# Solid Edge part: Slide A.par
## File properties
Author: davee
Template: Normal.par
Last saved by: davee
Revision: 2
Application: Solid Edge
Accuracy: 0.990
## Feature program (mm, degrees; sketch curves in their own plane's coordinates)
body "unnamed Body 1"
sketch for "unnamed Cutout 1" plane through (42.5, 0, 0) normal (0, 0, 1) x-axis (1, 0, 0)
  line (38.4225, -8.5675) -> (-42.5, -8.5675)
  line (38.4225, -71.4325) -> (38.4225, -8.5675)
  line (-42.5, -71.4325) -> (38.4225, -71.4325)
extrude "unnamed Cutout 1" cut to key point along -normal
sketch for "unnamed Cutout 2" #1 plane through (42.5, 0, 0) normal (0, 0, 1) x-axis (1, 0, 0)
  circle centre (20.12, -25.86) radius 2.6929
sketch for "unnamed Cutout 2" #2 plane through (42.5, 0, 0) normal (0, 0, 1) x-axis (1, 0, 0)
  arc centre (20.0176, -33.9386) radius 3.2974 from (16.7201, -33.9386) to (20.0176, -30.6411) cw
  line (20.0176, -30.6411) -> (20.2224, -30.6411)
  arc centre (20.2224, -33.9386) radius 3.2974 from (20.2224, -30.6411) to (23.5199, -33.9386) cw
  line (23.5199, -33.9386) -> (23.5199, -46.0614)
  arc centre (20.2224, -46.0614) radius 3.2974 from (23.5199, -46.0614) to (20.2224, -49.3589) cw
  line (20.2224, -49.3589) -> (20.0176, -49.3589)
  arc centre (20.0176, -46.0614) radius 3.2974 from (20.0176, -49.3589) to (16.7201, -46.0614) cw
  line (16.7201, -46.0614) -> (16.7201, -33.9386)
sketch for "unnamed Cutout 2" #3 plane through (42.5, 0, 0) normal (0, 0, 1) x-axis (1, 0, 0)
  circle centre (20.12, -54.14) radius 2.6929
extrude "unnamed Cutout 2" cut to key point along -normal
sketch for "unnamed Cutout 3" plane through (28.2602, -40, -11.1675) normal (0, 0, 1) x-axis (1, 0, 0)
  line (-30.5996, -17.2339) -> (29.2788, -17.2339)
  line (29.2788, -17.2339) -> (29.2788, 16.4162)
  line (29.2788, 16.4162) -> (-30.5996, 16.4162)
  line (-30.5996, 16.4162) -> (-30.5996, -17.2339)
extrude "unnamed Cutout 3" cut finite 15 along -normal
sketch for "ExtrudedCutout_8" plane through (0, 52.095, -35) normal (-1, 0, 0) x-axis (0, -1, 0)
  line (75.935, 23.8325) -> (108.255, 23.8325)
extrude "ExtrudedCutout_8" cut finite 171.45 along -normal
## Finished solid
Body 1: solid body, 135 faces, 331 edges, 196 vertices.
  Faces by surface: cylinder 62, plane 50, spline 11, sphere 6, torus 6
  Edges by curve: line 200, circle 71, ellipse 45, intersection 10, curve on surface 3, spline 2
Bounding box of the edges (mm; curved faces can reach further): 108.658 x 250.000 x 70.002, from (0, -125, -70.0017) to (108.6581, 125, 0).
Cylindrical faces by radius (mm): R0.7575 x13, R0.808 x3, R1.01 x39, R3.03 x4, R8.25 x2, R10.1 x1
Toroidal faces (ring radius, tube radius in mm): R2.02 r1.01 x4, R2.222 r0.808 x2
Spherical faces by radius (mm): R1.01 x6
Planar faces by outward normal: +x 1, +y 7, +z 5, -x 10, -y 7, -z 9, oblique 11
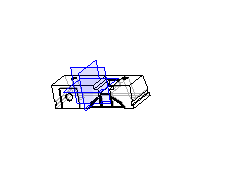
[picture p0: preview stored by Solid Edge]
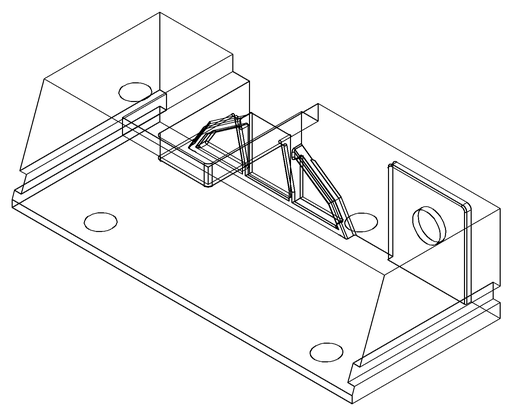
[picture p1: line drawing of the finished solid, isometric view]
